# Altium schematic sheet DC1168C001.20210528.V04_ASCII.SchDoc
size A3; Revision: V04; SheetNumber: 1; SheetTotal: 1
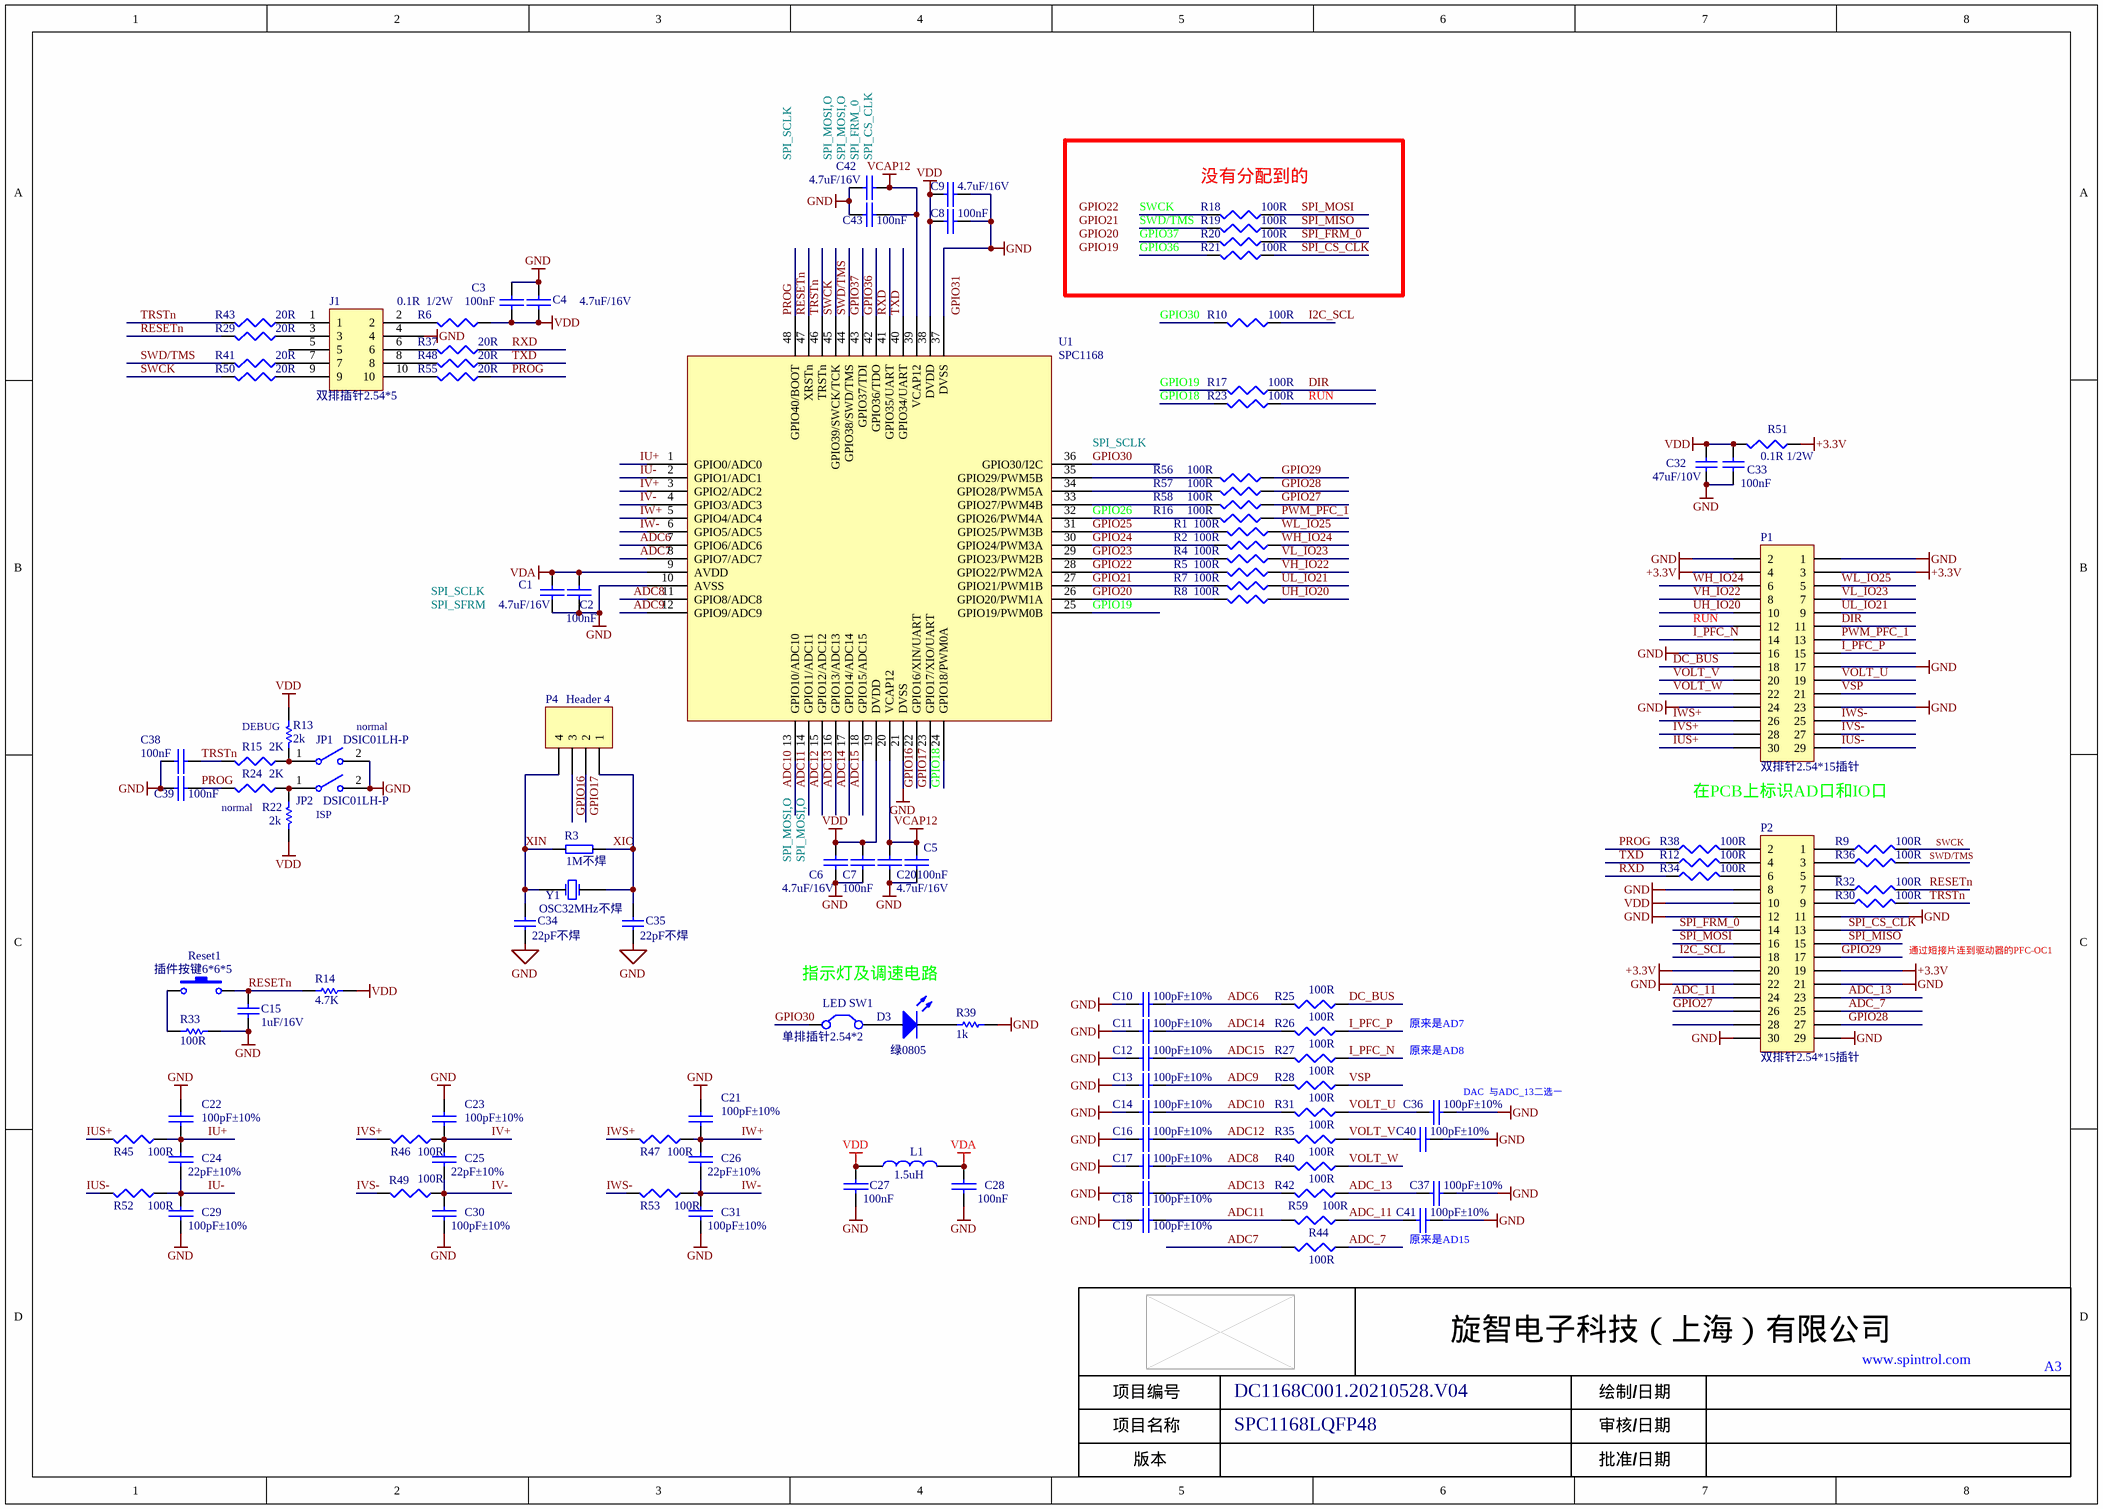
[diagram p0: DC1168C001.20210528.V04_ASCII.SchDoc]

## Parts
C1  4.7uF/16V  [0603]
C2  100nF  [0603]
C3  100nF  [0603]
C4  4.7uF/16V  [0603]
C5  100nF  [0603]
C6  4.7uF/16V  [0603]
C7  100nF  [0603]
C8  100nF  [0603]
C9  4.7uF/16V  [0603]
C10  100pF±10%  [0603]
C11  100pF±10%  [0603]
C12  100pF±10%  [0603]
C13  100pF±10%  [0603]
C14  100pF±10%  [0603]
C15  1uF/16V  [0603]
C16  100pF±10%  [0603]
C17  100pF±10%  [0603]
C18  100pF±10%  [0603]
C19  100pF±10%  [0603]
C20  4.7uF/16V  [0603]
C21  100pF±10%  [0603]
C22  100pF±10%  [0603]
C23  100pF±10%  [0603]
C24  22pF±10%  [0603]
C25  22pF±10%  [0603]
C26  22pF±10%  [0603]
C27  100nF  [0603]
C28  100nF  [0603]
C29  100pF±10%  [0603]
C30  100pF±10%  [0603]
C31  100pF±10%  [0603]
C32  47uF/10V  [1206]
C33  100nF  [0603]
C34  22pF不焊  [0603]
C35  22pF不焊  [0603]
C36  100pF±10%  [0603]
C37  100pF±10%  [0603]
C38  100nF  [0603]
C39  100nF  [0603]
C40  100pF±10%  [0603]
C41  100pF±10%  [0603]
C42  4.7uF/16V  [0603]
C43  100nF  [0603]
D3  绿0805  [led0805]
J1  双排插针2.54*5  [HDR2X5]
JP1  DSIC01LH-P  [S7.62*1]
JP2  DSIC01LH-P  [S7.62*1]
L1  1.5uH  [1206]
LED_SW1  单排插针2.54*2  [CON2]
P1  双排针2.54*15插针  [HDR2X15]
P2  双排针2.54*15插针  [HDR2X15]
P4  Header 4  [HDR1X4]
R1  100R  [0603]
R2  100R  [0603]
R3  1M不焊  [0603]
R4  100R  [0603]
R5  100R  [0603]
R6  0.1R  1/2W  [1210]
R7  100R  [0603]
R8  100R  [0603]
R9  100R  [0603]
R10  100R  [0603]
R12  100R  [0603]
R13  2k  [0603]
R14  4.7K  [0603]
R15  2K  [0603]
R16  100R  [0603]
R17  100R  [0603]
R18  100R  [0603]
R19  100R  [0603]
R20  100R  [0603]
R21  100R  [0603]
R22  2k  [0603]
R23  100R  [0603]
R24  2K  [0603]
R25  100R  [0603]
R26  100R  [0603]
R27  100R  [0603]
R28  100R  [0603]
R29  20R  [0805]
R30  100R  [0603]
R31  100R  [0603]
R32  100R  [0603]
R33  100R  [0603]
R34  100R  [0603]
R35  100R  [0603]
R36  100R  [0603]
R37  20R  [0805]
R38  100R  [0603]
R39  1k  [0603]
R40  100R  [0603]
R41  20R  [0805]
R42  100R  [0603]
R43  20R  [0805]
R44  100R  [0603]
R45  100R  [0603]
R46  100R  [0603]
R47  100R  [0603]
R48  20R  [0805]
R49  100R  [0603]
R50  20R  [0805]
R51  0.1R 1/2W  [1210]
R52  100R  [0603]
R53  100R  [0603]
R55  20R  [0805]
R56  100R  [0603]
R57  100R  [0603]
R58  100R  [0603]
R59  100R  [0603]
Reset1  插件按键6*6*5  [SW-TACT-6X6]
U1  SPC1168  [PQFP48]
Y1  OSC32MHz不焊  [OSC]

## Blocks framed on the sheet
没有分配到的: R18-R21

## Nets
+3.3V: P1.3 P1.4 P2.19 P2.20 R51.1
GND: C1.2 C2.2 C3.2 C4.1 C5.2 C6.2 C7.2 C8.2 C9.2 C10.2 C11.2 C12.2 C13.2 C14.2 C15.2 C16.2 C17.2 C18.2 C19.2 C20.2 C21.2 C22.2 C23.2 C27.1 C28.1 C29.2 C30.2 C31.2 C32.2 C33.2 C34.1 C35.1 C36.2 C37.2 C38.2 C39.2 C40.2 C41.2 C42.2 C43.2 J1.4 JP1.2 JP2.2 P1.1 P1.2 P1.16 P1.17 P1.23 P1.24 P2.8 P2.11 P2.12 P2.21 P2.22 P2.29 P2.30 R33.1 R39.1 U1.10(AVSS) U1.21(DVSS) U1.37(DVSS)
VCAP12: C5.1 C20.1 C42.1 C43.1 U1.20(VCAP12) U1.39(VCAP12)
VDA: C1.1 C2.1 C28.2 L1.2 U1.9(AVDD)
VDD: C3.1 C4.2 C6.1 C7.1 C8.1 C9.1 C27.2 C32.1 C33.1 L1.1 P2.10 R6.1 R13.2 R14.2 R22.1 R51.2 U1.19(DVDD) U1.38(DVDD)
ADC6: C10.1 R25.2 U1.7(GPIO6/ADC6)
ADC7: R44.2 U1.8(GPIO7/ADC7)
ADC8: C17.1 R40.2 U1.11(GPIO8/ADC8)
ADC9: C13.1 R28.2 U1.12(GPIO9/ADC9)
ADC10: C14.1 R31.2 U1.13(GPIO10/ADC10)
ADC11: C19.1 R59.2 U1.14(GPIO11/ADC11)
ADC12: C16.1 R35.2 U1.15(GPIO12/ADC12)
ADC13: C18.1 R42.2 U1.16(GPIO13/ADC13)
ADC14: C11.1 R26.2 U1.17(GPIO14/ADC14)
ADC15: C12.1 R27.2 U1.18(GPIO15/ADC15)
ADC_7: P2.25 R44.1
ADC_11: C41.1 P2.24 R59.1
ADC_13: C37.1 P2.23 R42.1
DC_BUS: P1.18 R25.1
DIR: P1.11 R17.1
GPIO16: P4.3 U1.22(GPIO16/XIN/UART)
GPIO17: P4.2 U1.23(GPIO17/XIO/UART)
GPIO18: R23.2 U1.24(GPIO18/PWM0A)
GPIO19: R17.2 U1.25(GPIO19/PWM0B)
GPIO20: R8.2 U1.26(GPIO20/PWM1A)
GPIO21: R7.2 U1.27(GPIO21/PWM1B)
GPIO22: R5.2 U1.28(GPIO22/PWM2A)
GPIO23: R4.2 U1.29(GPIO23/PWM2B)
GPIO24: R2.2 U1.30(GPIO24/PWM3A)
GPIO25: R1.2 U1.31(GPIO25/PWM3B)
GPIO26: R16.2 U1.32(GPIO26/PWM4A)
GPIO27: P2.26 R58.1
GPIO28: P2.27 R57.1
GPIO29: P2.17 R56.1
GPIO30: LED_SW1.1(C1) R10.2 U1.36(GPIO30/I2C)
GPIO36: R21.2 U1.42(GPIO36/TDO)
GPIO37: R20.2 U1.43(GPIO37/TDI)
I2C_SCL: P2.18 R10.1
I_PFC_N: P1.14 R27.1
I_PFC_P: P1.15 R26.1
IU+: C22.1 C24.1 R45.1 U1.1(GPIO0/ADC0)
IU-: C24.2 C29.1 R52.1 U1.2(GPIO1/ADC1)
IUS+: P1.30 R45.2
IUS-: P1.29 R52.2
IV+: C23.1 C25.1 R46.1 U1.3(GPIO2/ADC2)
IV-: C25.2 C30.1 R49.1 U1.4(GPIO3/ADC3)
IVS+: P1.28 R46.2
IVS-: P1.27 R49.2
IW+: C21.1 C26.1 R47.1 U1.5(GPIO4/ADC4)
IW-: C26.2 C31.1 R53.1 U1.6(GPIO5/ADC5)
IWS+: P1.26 R47.2
IWS-: P1.25 R53.2
PROG: C39.1 R24.2 R38.1 R55.1 U1.48(GPIO40/BOOT)
PWM_PFC_1: P1.13 R16.1
RESETn: C15.1 R14.1 R29.2 R32.2 Reset1.1 U1.47(XRSTn)
RUN: P1.12 R23.1
RXD: R34.1 R37.1 U1.41(GPIO35/UART)
SPI_CS_CLK: P2.13 R21.1
SPI_FRM_0: P2.14 R20.1
SPI_MISO: P2.15 R19.1
SPI_MOSI: P2.16 R18.1
SWCK: R9.2 R18.2 R50.2 U1.45(GPIO39/SWCK/TCK)
SWD/TMS: R19.2 R36.2 R41.2 U1.44(GPIO38/SWD/TMS)
TRSTn: C38.1 R15.2 R30.2 R43.2 U1.46(TRSTn)
TXD: R12.1 R48.1 U1.40(GPIO34/UART)
UH_IO20: P1.10 R8.1
UL_IO21: P1.9 R7.1
VH_IO22: P1.8 R5.1
VL_IO23: P1.7 R4.1
VOLT_U: C36.1 P1.19 R31.1
VOLT_V: C40.1 P1.20 R35.1
VOLT_W: P1.22 R40.1
VSP: P1.21 R28.1
WH_IO24: P1.6 R2.1
WL_IO25: P1.5 R1.1
XIN: C34.2 P4.4 R3.1 Y1.1(OSC1)
XIO: C35.2 P4.1 R3.2 Y1.2(OSC2)
NetD3_1: D3.1(A) LED_SW1.2(C2)
NetD3_2: D3.2(K) R39.2
NetJ1_1: J1.1 R43.1
NetJ1_2: J1.2 R6.2
NetJ1_3: J1.3 R29.1
NetJ1_6: J1.6 R37.2
NetJ1_7: J1.7 R41.1
NetJ1_8: J1.8 R48.2
NetJ1_9: J1.9 R50.1
NetJ1_10: J1.10 R55.2
NetJP1_1: JP1.1 R13.1 R15.1
NetJP2_1: JP2.1 R22.2 R24.1
NetP2_1: P2.1 R9.1
NetP2_2: P2.2 R38.2
NetP2_3: P2.3 R36.1
NetP2_4: P2.4 R12.2
NetP2_6: P2.6 R34.2
NetP2_7: P2.7 R32.1
NetP2_9: P2.9 R30.1
NetR33_2: R33.2 Reset1.2
NetR56_2: R56.2 U1.35(GPIO29/PWM5B)
NetR57_2: R57.2 U1.34(GPIO28/PWM5A)
NetR58_2: R58.2 U1.33(GPIO27/PWM4B)

Not connected (* = marked no-connect by the designer): J1 5; P2 5 28

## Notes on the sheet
- DEBUG
- (near JP1) normal
- (near R24) normal
- ISP
- 在PCB上标识AD口和IO口
- 指示灯及调速电路
- 通过短接片连到驱动器的PFC-OC1
- 原来是AD8
- 原来是AD7
- (near C36) DAC  与ADC_13二选一
- (near C41) 原来是AD15
- DC1168C001.20210528.V04
- SPC1168LQFP48
- Labels drawn without touching a wire or pin: GPIO19, GPIO20, GPIO21, GPIO22, GPIO31, SPI_CS_CLK, SPI_FRM_0, SPI_MOSI,O, SPI_SCLK, SPI_SFRM

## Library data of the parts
C1 C2 C4-C14 C16-C26 C29-C31 C36-C43 = CAP-CC(SMD): Capacitor
C3 = CAP-CC: Capacitor
C15 C32 C33 = Cap: Capacitor
C27 C28 = CAP-CC
C34 C35 = Capacitor Unpolarized: CAP CER 20PF 10V X7R 0603
D3 = LED2: FC-2012UGK-520D5
J1 = CON10_BI: ISP SOCKET
JP1 JP2 = SW-2
L1 = INDUCTOR1
LED_SW1 = Jumper: Jumper Wire
P1 P2 = Header 15X2: Header, 15-Pin, Dual row
P4 = Header 4: Header, 4-Pin
R1 R2 R4-R10 R12 R15-R21 R23-R32 R34-R38 R40-R53 R55-R59 = RES(SMD)
R3 = Resistor
R13 R14 R22 R33 R39 = Res1: Resistor
Reset1 = SW-PB: Switch
U1 = GECKO: 32-bit ARM CM4 MCU
Y1 = OSC32MHz: CRYSTAL 32.0000MHZ 20PF T/H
